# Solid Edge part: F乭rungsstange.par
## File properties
Username: bmolnar
Dokumentum tartalom típus: 0
Author: bmolnar
Last saved by: bmolnar
Revision: 77
Sűrűség: 0,000 kg/m^3
Pontosság: 0,990
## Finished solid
Body 1: solid body, 8 faces, 7 edges, 5 vertices.
  Faces by surface: cone 4, cylinder 2, plane 2
  Edges by curve: circle 7
Bounding box of the edges (mm): 6.000 x 6.000 x 55.000, from (-3, -3, -30) to (3, 3, 25).
Cylindrical faces by radius (mm): R1.621 x1, R3 x1
Conical faces (half-angle, radius in mm at the cone's reference point): 45 deg R1.721 x1, 45 deg R2.75 x1, 45 deg R2.9 x1, 59 deg R0.8105 x1
Planar faces by outward normal: +z 1, -z 1
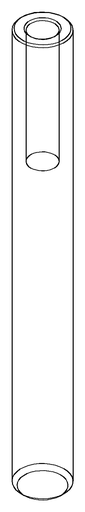
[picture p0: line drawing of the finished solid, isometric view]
